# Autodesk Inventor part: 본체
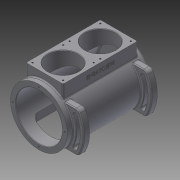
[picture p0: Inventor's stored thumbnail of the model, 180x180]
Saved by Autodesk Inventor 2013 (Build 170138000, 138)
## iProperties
Created: 2016-11
Part Number: 본체
Material: 일반
Document SubType Name: Modeling
Designer: mduedu
Density: 1 g/cm^3
Author: mduedu
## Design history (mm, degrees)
sketch "스케치1"
  geometry: C1 r 65 at (0, 0); 1 further point
  constraints: 1 centre point, 1 coincident
  dimensions: "d119" = 130 diameter of C1
extrude "돌출1" new body sketch "스케치1" distance "d3" = 98; taper "d4" = 0 deg; dims "d132" = 97, "d133" = 0
feature "쉘1" dims "d120" = 12, "d134" = 8
node "작업 평면2"
sketch "스케치13"
  geometry: L1 (42.5, 85)-(-42.5, 85); L2 (-42.5, 85)-(-42.5, -85); L3 (-42.5, -85)-(42.5, -85); L4 (42.5, -85)-(42.5, 85); 2 further points
  constraints: 8 end point, 2 parallel, 1 horizontal, 1 midpoint, 1 perpendicular, 1 vertical alignment
  dimensions: "d122" = 170 distance of L1.end L2.end; "d124" = 85 distance of L2.end L3.end; "d125" = 85 distance from line of point (0, 0) L1 (= 0.5 x d122)
extrude "돌출11" join sketch "스케치13" stored distance "d126" = 10; taper "d127" = 0 deg
sketch "스케치14"
  geometry: L1 (65, 97)-(-65, 97) reference; C1 r 35 at (0, 42.5); 1 further point
  constraints: 1 centre point, 1 vertical alignment
  dimensions: "d128" = 70 diameter of C1; "d129" = 54.5 distance from line of C1.centre L1
extrude "돌출12" cut sketch "스케치14" stored distance "d130" = 10; taper "d131" = 0 deg
sketch "스케치15"
  geometry: C1 r 53 at (0, 0) reference; 1 further point
extrude "돌출13" cut sketch "스케치15" stored distance "d135" = 10; taper "d136" = 0 deg
chamfer "모따기1" distance "d54" = 1; stored, may be unused: second distance "d55" = 2, angle "d56" = 45 deg
sketch "스케치8"
  geometry: C1 r 30 at (0, 0); C2 r 65 at (0, 0) reference; 1 further point
  constraints: 1 centre point, 1 concentric
  dimensions: "d57" = 60 diameter of C1
extrude "돌출8" join sketch "스케치8" distance "d58" = 14; taper "d59" = 0 deg
hole "구멍3" diameter "d62" = 41; stored, may be unused: countersink angle "d66" = 90 deg, drill point angle "d68" = 0 deg; dims "d63" = 6, "d64" = 47, "d65" = 14, "d67" = 17, "d195" = 10, "d196" = 10
fillet "모깎기11" dims "d69" = 3
fillet "모깎기12" dims "d70" = 3
fillet "모깎기13" dims "d71" = 0.3
chamfer "모따기2" distance "d72" = 1; stored, may be unused: second distance "d73" = 2, angle "d74" = 45 deg
node "작업 평면3"
sketch "스케치16"
  geometry: L1 (-42.5, -80)-(47.5, -80); L2 (-42.5, -80)-(21.14, -16.36); L3 (-42.5, -80)-(21.14, -143.64); L4 (3.462, -34.038)-(34.879, -34.038); L5 (3.462, -125.962)-(34.879, -125.962); A1 r 65 centre (-42.5, -80) between (3.462, -34.038) and (3.462, -125.962) reference; A2 r 90 centre (-42.5, -80) between (34.879, -125.962) and (34.879, -34.038); A3 r 90 centre (-42.5, -80) between (34.879, -34.038) and (34.879, -125.962); A4 r 65 centre (-42.5, -80) between (3.462, -125.962) and (3.462, -34.038); 1 further point
  constraints: 11 point on circle, 10 end point, 3 centre point, 2 parallel, 2 point on line, 1 coincident, 1 horizontal
  dimensions: "d140" = 45 deg angle of L3 L1; "d141" = 45 deg angle of L2 L1; "d142" = 25 radial gap between concentric circles of A1 A2
extrude "돌출14" join sketch "스케치16" distance "d143" = 15; taper "d144" = 0 deg
sketch "스케치17"
  geometry: L1 (-42.5, -80)-(34.414, -80); L2 (-42.5, -80)-(27.208, -47.495); L3 (-42.5, -80)-(27.208, -112.505); L4 (34.879, -34.038)-(3.462, -34.038) reference; L5 (3.462, -125.962)-(34.879, -125.962) reference; A1 r 65 centre (-42.5, -80) between (3.462, -34.038) and (3.462, -125.962) reference; A2 r 76.914 centre (-42.5, -80) between (19.17, -125.962) and (19.17, -34.038); A3 r 4 centre (27.208, -47.495) between (23.582, -49.185) and (30.833, -45.804); A4 r 4 centre (27.208, -112.505) between (30.833, -114.196) and (23.582, -110.815); A5 r 80.914 centre (-42.5, -80) between (30.833, -114.196) and (30.833, -45.804); A6 r 72.914 centre (-42.5, -80) between (23.582, -110.815) and (23.582, -49.185); 1 further point
  constraints: 13 point on circle, 6 end point, 5 centre point, 5 coincident, 3 midpoint, 2 point on line, 1 equal radius, 1 horizontal
  dimensions: "d145" = 25 deg angle of L1 L3; "d146" = 25 deg angle of L2 L1; "d147" = 8 diameter of A3
extrude "돌출15" cut sketch "스케치17" stored distance "d150" = 15; taper "d151" = 0 deg
fillet "모깎기17" dims "d152" = 10
fillet "모깎기18" dims "d153" = 2
fillet "모깎기19" dims "d154" = 2
chamfer "모따기4" distance "d155" = 1; stored, may be unused: second distance "d156" = 2, angle "d157" = 45 deg
fillet "모깎기20" dims "d159" = 3
fillet "모깎기21" dims "d160" = 3
fillet "모깎기22" dims "d161" = 3
node "작업 평면4"
sketch "스케치18"
  geometry: L1 (-42.5, 70)-(42.5, 70); L2 (42.5, 70)-(42.5, -70); L3 (42.5, -70)-(-42.5, -70); L4 (-42.5, -70)-(-42.5, 70); 2 further points
  constraints: 8 end point, 2 parallel, 1 horizontal, 1 midpoint, 1 perpendicular, 1 vertical alignment
  dimensions: "d162" = 140 distance of L1.end L2.end; "d164" = 85 distance of L2.end L3.end; "d165" = 70 distance from line of point (0, 0) L1 (= 0.5 x d162)
extrude "돌출16" cut sketch "스케치18" stored distance "d166" = 15; taper "d167" = 0 deg
fillet "모깎기23" dims "d168" = 10
fillet "모깎기24" dims "d173" = 3
sketch "스케치19"
  geometry: 4 further points
  constraints: 4 other
hole "구멍6" sketch "스케치19" at (0, -59), (59, 0), (-59, 0), (0, 59) diameter "d174" = 3.242; stored, may be unused: countersink angle "d178" = 90 deg, drill point angle "d180" = 120 deg; dims "d175" = 8, "d176" = 4, "d177" = 2, "d179" = 10
sketch "스케치20"
  geometry: L1 (35, -77.5)-(-35, -77.5); L2 (-35, -77.5)-(-35, -7.5); L3 (-35, -7.5)-(35, -7.5); L4 (35, -7.5)-(35, -77.5); L5 (35, -77.5)-(-35, -7.5); L6 (-35, -77.5)-(35, -7.5); C1 r 36 at (0, -42.5) reference; 5 further points
  constraints: 12 end point, 4 coincident, 2 midpoint, 2 parallel, 1 horizontal, 1 perpendicular
  dimensions: "d181" = 70 distance of L2.end L3.end; "d182" = 70 distance of L1.end L2.end
hole "구멍7" sketch "스케치20" at (-35, -77.5), (-35, -7.5), (35, -7.5), (35, -77.5) diameter "d183" = 3.242; stored, may be unused: countersink angle "d187" = 90 deg, drill point angle "d189" = 118 deg; dims "d184" = 8, "d185" = 4, "d186" = 2, "d188" = 10
sketch "스케치21"
  geometry: L1 (164, 0)-(0, 0) reference; L2 (-3, 0)-(-3, -24.649) reference; 3 further points
  constraints: 1 midpoint, 1 vertical alignment, 1 other
  dimensions: "d190" = 15 distance from line of point (82, -15) L1; "d191" = 85 distance from line of point (82, 0) L2 (derived)
feature "엠보싱2" sketch "스케치21" dims "d3" = 98, "d4" = 0, "d119" = 130, "d132" = 97, "d133" = 0, "d192" = 0.5, "d193" = 0
node "솔리드1"
mirror "대칭5"
mirror "대칭6"
mirror "대칭7"
